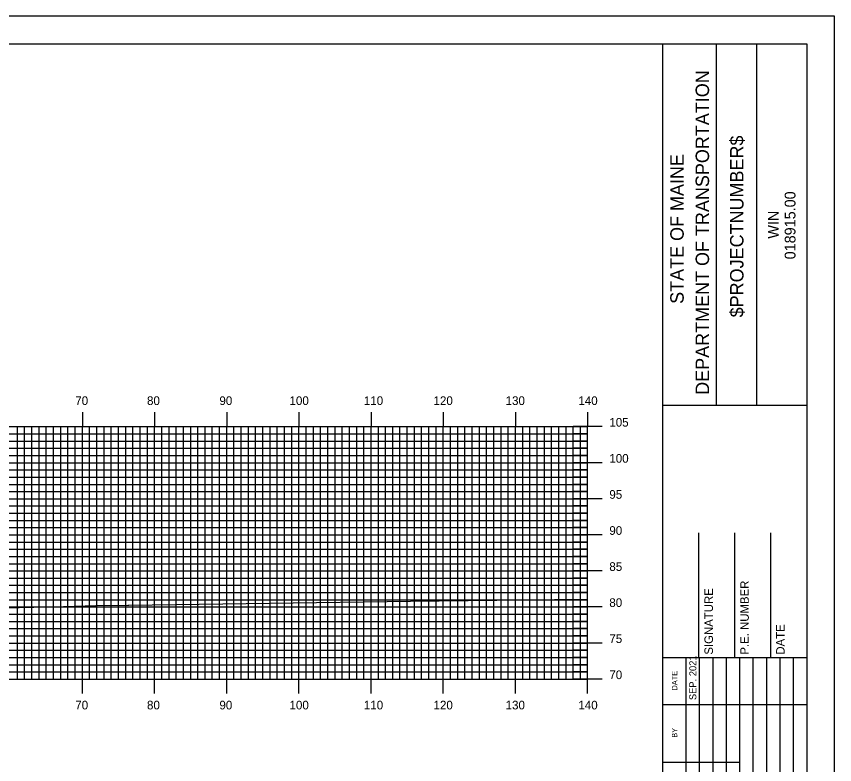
# Model space of a CAD drawing. Extents: x 1756675 to 1757019, y 442591 to 442811.
# Drawn here: x 1756901.9 to 1757015.3, y 442706.8 to 442810.5 of the extents above; entities that cross this region are included whole.
import ezdxf

# ---------------------------------------------------------------- set-up
doc = ezdxf.new("R2010")
doc.units = 0
for name, color, linetype in [('BORDER', 7, 'Continuous'), ('D_Roadway_SubGrade', 7, 'Continuous'), ('H_V ANNOTATION', 7, 'Continuous'), ('MAJOR', 7, 'Continuous'), ('MINOR', 7, 'Continuous'), ('PLOT BOUNDARY', 7, 'Continuous'), ('S_Roadway_Centerline', 7, 'Continuous')]:
    doc.layers.add(name, color=color, linetype=linetype)

msp = doc.modelspace()

# ---------------------------------------------------------------- linework, layer by layer
at = {"layer": 'BORDER'}
for p, q in [((1756991.48, 442596.67), (1756991.48, 442806.67)), ((1756998.94, 442756.66), (1756998.94, 442806.66)), ((1757004.53, 442756.66), (1757004.53, 442806.66)), ((1756991.48, 442756.65), (1757011.48, 442756.65)), ((1756996.48, 442721.67), (1756996.48, 442738.97)), ((1757001.48, 442721.67), (1757001.48, 442738.97)), ((1757006.48, 442721.67), (1757006.48, 442738.97)), ((1756991.48, 442721.67), (1757011.48, 442721.67))]:
    msp.add_line(p, q, dxfattribs=at)
msp.add_lwpolyline([(1756691.48, 442596.67), (1757011.48, 442596.67), (1757011.48, 442806.67), (1756691.48, 442806.67)], close=True, dxfattribs=at)
for points in [[(1756994.71, 442715.17), (1756994.71, 442721.67)], [(1756996.58, 442686.68), (1756996.58, 442721.67)], [(1756998.44, 442721.67), (1756998.44, 442686.68)], [(1757000.3, 442686.68), (1757000.3, 442721.67)], [(1757002.17, 442686.68), (1757002.17, 442721.67)], [(1757004.03, 442686.68), (1757004.03, 442721.67)], [(1757005.89, 442686.68), (1757005.89, 442721.67)], [(1757007.76, 442686.68), (1757007.76, 442721.67)], [(1757009.62, 442686.68), (1757009.62, 442721.67)], [(1756994.71, 442686.68), (1756994.71, 442720.26)], [(1756991.48, 442715.17), (1757011.48, 442715.17)], [(1756991.48, 442707.17), (1756994.71, 442707.17)], [(1756994.71, 442707.17), (1757002.17, 442707.17)]]:
    msp.add_lwpolyline(points, dxfattribs=at)
at = {"layer": 'D_Roadway_SubGrade'}
msp.add_line((1756981.08, 442738.67), (1756981.08, 442743.31), dxfattribs=at)
at = {"layer": 'MAJOR'}
for p, q in [((1756911.08, 442755.67), (1756911.08, 442753.67)), ((1756921.08, 442755.67), (1756921.08, 442753.67)), ((1756931.08, 442755.67), (1756931.08, 442753.67)), ((1756941.08, 442755.67), (1756941.08, 442753.67)), ((1756951.08, 442755.67), (1756951.08, 442753.67)), ((1756961.08, 442755.67), (1756961.08, 442753.67)), ((1756971.08, 442755.67), (1756971.08, 442753.67)), ((1756981.08, 442755.67), (1756981.08, 442753.67)), ((1756701.08, 442753.67), (1756981.08, 442753.67)), ((1756701.08, 442753.67), (1756981.08, 442753.67)), ((1756911.08, 442718.67), (1756911.08, 442753.67)), ((1756921.08, 442718.67), (1756921.08, 442753.67)), ((1756931.08, 442718.67), (1756931.08, 442753.67)), ((1756941.08, 442718.67), (1756941.08, 442753.67)), ((1756951.08, 442718.67), (1756951.08, 442753.67)), ((1756961.08, 442718.67), (1756961.08, 442753.67)), ((1756971.08, 442718.67), (1756971.08, 442753.67)), ((1756983.09, 442753.67), (1756979.08, 442753.67)), ((1756981.08, 442718.67), (1756981.08, 442753.67)), ((1756981.08, 442718.67), (1756981.08, 442753.67)), ((1756701.08, 442748.67), (1756981.08, 442748.67)), ((1756983.09, 442748.67), (1756979.08, 442748.67)), ((1756701.08, 442743.67), (1756981.08, 442743.67)), ((1756983.09, 442743.67), (1756979.08, 442743.67)), ((1756701.08, 442738.67), (1756981.08, 442738.67)), ((1756983.09, 442738.67), (1756979.08, 442738.67)), ((1756701.08, 442733.67), (1756981.08, 442733.67)), ((1756983.09, 442733.67), (1756979.08, 442733.67)), ((1756701.08, 442728.67), (1756981.08, 442728.67)), ((1756983.09, 442728.67), (1756979.08, 442728.67)), ((1756701.08, 442723.67), (1756981.08, 442723.67)), ((1756983.09, 442723.67), (1756979.08, 442723.67)), ((1756701.08, 442718.67), (1756981.08, 442718.67)), ((1756701.08, 442718.67), (1756981.08, 442718.67)), ((1756911.08, 442716.66), (1756911.08, 442718.67)), ((1756921.08, 442716.66), (1756921.08, 442718.67)), ((1756931.08, 442716.66), (1756931.08, 442718.67)), ((1756941.08, 442716.66), (1756941.08, 442718.67)), ((1756951.08, 442716.66), (1756951.08, 442718.67)), ((1756961.08, 442716.66), (1756961.08, 442718.67)), ((1756971.08, 442716.66), (1756971.08, 442718.67)), ((1756983.09, 442718.67), (1756979.08, 442718.67)), ((1756981.08, 442716.66), (1756981.08, 442718.67))]:
    msp.add_line(p, q, dxfattribs=at)
at = {"layer": 'MINOR'}
for p, q in [((1756902.08, 442718.67), (1756902.08, 442753.67)), ((1756903.08, 442718.67), (1756903.08, 442753.67)), ((1756904.08, 442718.67), (1756904.08, 442753.67)), ((1756905.08, 442718.67), (1756905.08, 442753.67)), ((1756906.08, 442718.67), (1756906.08, 442753.67)), ((1756907.08, 442718.67), (1756907.08, 442753.67)), ((1756908.08, 442718.67), (1756908.08, 442753.67)), ((1756909.08, 442718.67), (1756909.08, 442753.67)), ((1756910.08, 442718.67), (1756910.08, 442753.67)), ((1756912.08, 442718.67), (1756912.08, 442753.67)), ((1756913.08, 442718.67), (1756913.08, 442753.67)), ((1756914.08, 442718.67), (1756914.08, 442753.67)), ((1756915.08, 442718.67), (1756915.08, 442753.67)), ((1756916.08, 442718.67), (1756916.08, 442753.67)), ((1756917.08, 442718.67), (1756917.08, 442753.67)), ((1756918.08, 442718.67), (1756918.08, 442753.67)), ((1756919.08, 442718.67), (1756919.08, 442753.67)), ((1756920.08, 442718.67), (1756920.08, 442753.67)), ((1756922.08, 442718.67), (1756922.08, 442753.67)), ((1756923.08, 442718.67), (1756923.08, 442753.67)), ((1756924.08, 442718.67), (1756924.08, 442753.67)), ((1756925.08, 442718.67), (1756925.08, 442753.67)), ((1756926.08, 442718.67), (1756926.08, 442753.67)), ((1756927.08, 442718.67), (1756927.08, 442753.67)), ((1756928.08, 442718.67), (1756928.08, 442753.67)), ((1756929.08, 442718.67), (1756929.08, 442753.67)), ((1756930.08, 442718.67), (1756930.08, 442753.67)), ((1756932.08, 442718.67), (1756932.08, 442753.67)), ((1756933.08, 442718.67), (1756933.08, 442753.67)), ((1756934.08, 442718.67), (1756934.08, 442753.67)), ((1756935.08, 442718.67), (1756935.08, 442753.67)), ((1756936.08, 442718.67), (1756936.08, 442753.67)), ((1756937.08, 442718.67), (1756937.08, 442753.67)), ((1756938.08, 442718.67), (1756938.08, 442753.67)), ((1756939.08, 442718.67), (1756939.08, 442753.67)), ((1756940.08, 442718.67), (1756940.08, 442753.67)), ((1756942.08, 442718.67), (1756942.08, 442753.67)), ((1756943.08, 442718.67), (1756943.08, 442753.67)), ((1756944.08, 442718.67), (1756944.08, 442753.67)), ((1756945.08, 442718.67), (1756945.08, 442753.67)), ((1756946.08, 442718.67), (1756946.08, 442753.67)), ((1756947.08, 442718.67), (1756947.08, 442753.67)), ((1756948.08, 442718.67), (1756948.08, 442753.67)), ((1756949.08, 442718.67), (1756949.08, 442753.67)), ((1756950.08, 442718.67), (1756950.08, 442753.67)), ((1756952.08, 442718.67), (1756952.08, 442753.67)), ((1756953.08, 442718.67), (1756953.08, 442753.67)), ((1756954.08, 442718.67), (1756954.08, 442753.67)), ((1756955.08, 442718.67), (1756955.08, 442753.67)), ((1756956.08, 442718.67), (1756956.08, 442753.67)), ((1756957.08, 442718.67), (1756957.08, 442753.67)), ((1756958.08, 442718.67), (1756958.08, 442753.67)), ((1756959.08, 442718.67), (1756959.08, 442753.67)), ((1756960.08, 442718.67), (1756960.08, 442753.67)), ((1756962.08, 442718.67), (1756962.08, 442753.67)), ((1756963.08, 442718.67), (1756963.08, 442753.67)), ((1756964.08, 442718.67), (1756964.08, 442753.67)), ((1756965.08, 442718.67), (1756965.08, 442753.67)), ((1756966.08, 442718.67), (1756966.08, 442753.67)), ((1756967.08, 442718.67), (1756967.08, 442753.67)), ((1756968.08, 442718.67), (1756968.08, 442753.67)), ((1756969.08, 442718.67), (1756969.08, 442753.67)), ((1756970.08, 442718.67), (1756970.08, 442753.67)), ((1756972.08, 442718.67), (1756972.08, 442753.67)), ((1756973.08, 442718.67), (1756973.08, 442753.67)), ((1756974.08, 442718.67), (1756974.08, 442753.67)), ((1756975.08, 442718.67), (1756975.08, 442753.67)), ((1756976.08, 442718.67), (1756976.08, 442753.67)), ((1756977.08, 442718.67), (1756977.08, 442753.67)), ((1756978.08, 442718.67), (1756978.08, 442753.67)), ((1756979.08, 442718.67), (1756979.08, 442753.67)), ((1756980.08, 442718.67), (1756980.08, 442753.67)), ((1756701.08, 442752.67), (1756981.08, 442752.67)), ((1756981.08, 442752.67), (1756979.08, 442752.67)), ((1756701.08, 442751.67), (1756981.08, 442751.67)), ((1756981.08, 442751.67), (1756979.08, 442751.67)), ((1756701.08, 442750.67), (1756981.08, 442750.67)), ((1756981.08, 442750.67), (1756979.08, 442750.67)), ((1756701.08, 442749.67), (1756981.08, 442749.67)), ((1756981.08, 442749.67), (1756979.08, 442749.67)), ((1756701.08, 442747.67), (1756981.08, 442747.67)), ((1756701.08, 442746.67), (1756981.08, 442746.67)), ((1756981.08, 442747.67), (1756979.08, 442747.67)), ((1756981.08, 442746.67), (1756979.08, 442746.67)), ((1756701.08, 442745.67), (1756981.08, 442745.67)), ((1756981.08, 442745.67), (1756979.08, 442745.67)), ((1756701.08, 442744.67), (1756981.08, 442744.67)), ((1756981.08, 442744.67), (1756979.08, 442744.67)), ((1756701.08, 442742.67), (1756981.08, 442742.67)), ((1756981.08, 442742.67), (1756979.08, 442742.67)), ((1756701.08, 442741.67), (1756981.08, 442741.67)), ((1756981.08, 442741.67), (1756979.08, 442741.67)), ((1756701.08, 442740.67), (1756981.08, 442740.67)), ((1756981.08, 442740.67), (1756979.08, 442740.67)), ((1756701.08, 442739.67), (1756981.08, 442739.67)), ((1756981.08, 442739.67), (1756979.08, 442739.67)), ((1756701.08, 442737.67), (1756981.08, 442737.67)), ((1756981.08, 442737.67), (1756979.08, 442737.67)), ((1756701.08, 442736.67), (1756981.08, 442736.67)), ((1756981.08, 442736.67), (1756979.08, 442736.67)), ((1756701.08, 442735.67), (1756981.08, 442735.67)), ((1756981.08, 442735.67), (1756979.08, 442735.67)), ((1756701.08, 442734.67), (1756981.08, 442734.67)), ((1756981.08, 442734.67), (1756979.08, 442734.67)), ((1756701.08, 442732.67), (1756981.08, 442732.67)), ((1756981.08, 442732.67), (1756979.08, 442732.67)), ((1756701.08, 442731.67), (1756981.08, 442731.67)), ((1756981.08, 442731.67), (1756979.08, 442731.67)), ((1756701.08, 442730.67), (1756981.08, 442730.67)), ((1756701.08, 442729.67), (1756981.08, 442729.67)), ((1756981.08, 442730.67), (1756979.08, 442730.67)), ((1756981.08, 442729.67), (1756979.08, 442729.67)), ((1756701.08, 442727.67), (1756981.08, 442727.67)), ((1756981.08, 442727.67), (1756979.08, 442727.67)), ((1756701.08, 442726.67), (1756981.08, 442726.67)), ((1756981.08, 442726.67), (1756979.08, 442726.67)), ((1756701.08, 442725.67), (1756981.08, 442725.67)), ((1756981.08, 442725.67), (1756979.08, 442725.67)), ((1756701.08, 442724.67), (1756981.08, 442724.67)), ((1756981.08, 442724.67), (1756979.08, 442724.67)), ((1756701.08, 442722.67), (1756981.08, 442722.67)), ((1756701.08, 442721.67), (1756981.08, 442721.67)), ((1756981.08, 442722.67), (1756979.08, 442722.67)), ((1756981.08, 442721.67), (1756979.08, 442721.67)), ((1756701.08, 442720.67), (1756981.08, 442720.67)), ((1756981.08, 442720.67), (1756979.08, 442720.67)), ((1756701.08, 442719.67), (1756981.08, 442719.67)), ((1756981.08, 442719.67), (1756979.08, 442719.67))]:
    msp.add_line(p, q, dxfattribs=at)
at = {"layer": 'PLOT BOUNDARY'}
msp.add_lwpolyline([(1756675.3, 442590.55), (1757015.3, 442590.55), (1757015.3, 442810.55), (1756675.3, 442810.55)], close=True, dxfattribs=at)
at = {"layer": 'S_Roadway_Centerline'}
msp.add_lwpolyline([(1756701.08, 442729.47), (1756728.63, 442729.61), (1756749.63, 442729.51), (1756753.73, 442729.53), (1756758.51, 442729.63), (1756775.1, 442729.71), (1756800.77, 442729.86), (1756805.16, 442729.75), (1756821.92, 442729.09), (1756848.37, 442728.26), (1756855.36, 442728.14), (1756864.2, 442727.97), (1756889.97, 442728.34), (1756908.46, 442728.73), (1756912.95, 442728.86), (1756917.38, 442728.94), (1756917.49, 442728.92), (1756956.52, 442729.49), (1756976.5, 442729.7), (1756981.08, 442729.72)], dxfattribs=at)

# ---------------------------------------------------------------- texts
at = {"layer": 'BORDER'}
for s, height, p in [('DEPARTMENT OF TRANSPORTATION', 1.8635, (1756997.9, 442758.08)), ('$PROJECTNUMBER$', 1.8635, (1757002.67, 442768.82)), ('STATE OF MAINE', 1.8635, (1756994.39, 442770.69)), ('018915.00', 1.491, (1757009.87, 442776.86)), ('WIN', 1.491, (1757007.56, 442779.73)), ('P.E. NUMBER', 1.1811, (1757003.4, 442722.06)), ('SIGNATURE', 1.181, (1756998.44, 442722.06)), ('DATE', 1.181, (1757008.37, 442722.06)), ('SEP. 2021', 0.969, (1756996.13, 442715.76)), ('DATE', 0.743, (1756993.49, 442717.08)), ('BY', 0.743, (1756993.49, 442710.54))]:
    msp.add_text(s, height=height, rotation=90, dxfattribs=at).set_placement(p)
at = {"layer": 'H_V ANNOTATION'}
for s, p in [('70', (1756910.09, 442756.67)), ('80', (1756920.03, 442756.67)), ('90', (1756930.06, 442756.67)), ('100', (1756939.77, 442756.67)), ('110', (1756950.07, 442756.67)), ('120', (1756959.72, 442756.67)), ('130', (1756969.71, 442756.67)), ('140', (1756979.79, 442756.67)), ('105', (1756984.08, 442753.67)), ('100', (1756984.08, 442748.67)), ('95', (1756984.08, 442743.67)), ('90', (1756984.08, 442738.67)), ('85', (1756984.08, 442733.67)), ('80', (1756984.08, 442728.67)), ('75', (1756984.08, 442723.67)), ('70', (1756984.08, 442718.67)), ('70', (1756910.09, 442714.47)), ('80', (1756920.03, 442714.47)), ('90', (1756930.06, 442714.47)), ('100', (1756939.77, 442714.47)), ('110', (1756950.07, 442714.47)), ('120', (1756959.72, 442714.47)), ('130', (1756969.71, 442714.47)), ('140', (1756979.79, 442714.47))]:
    msp.add_text(s, height=1.2, dxfattribs=at).set_placement(p)

doc.saveas('drawing.dxf')
